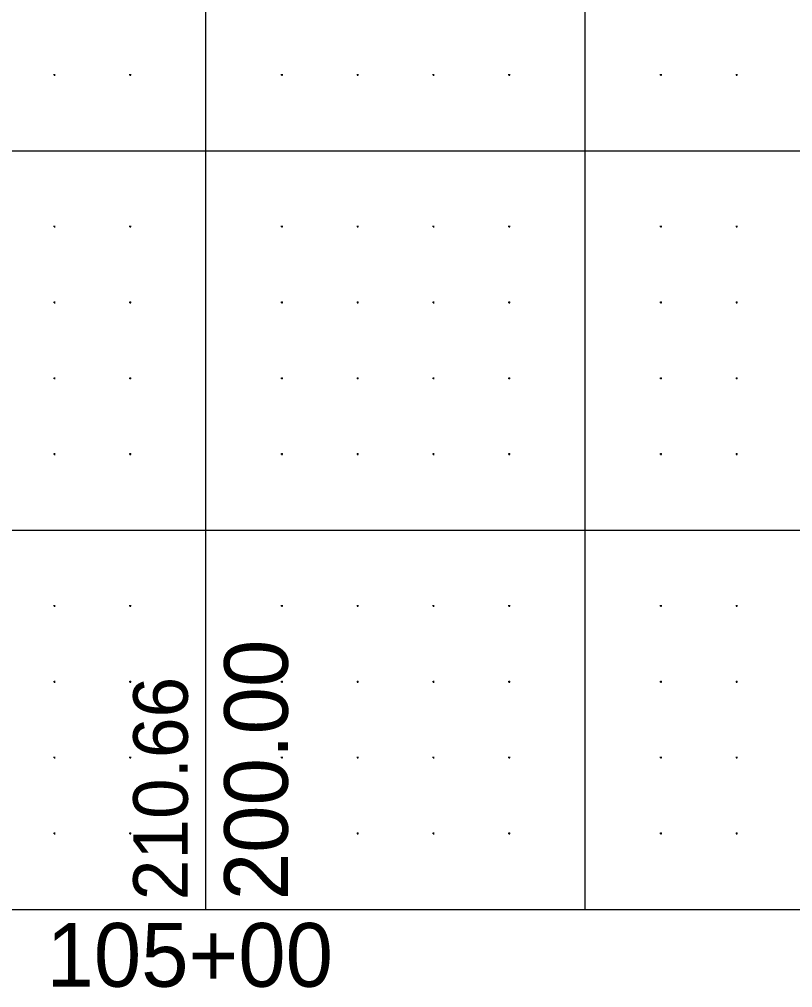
# Model space of a CAD drawing. Extents: x 471 to 2121, y 140 to 650.
# Drawn here: x 1111.4 to 1213.4, y 139.7 to 267.3 of the extents above; entities that cross this region are included whole.
import ezdxf

# ---------------------------------------------------------------- set-up
doc = ezdxf.new("R2010")
doc.units = 0
for name, color, linetype in [('DSN_DRFT_Border Grid', 7, 'Continuous'), ('DSN_RDWY_Prof Annotation', 7, 'Continuous'), ('EX_Profile Annotation', 7, 'Continuous')]:
    doc.layers.add(name, color=color, linetype=linetype)

msp = doc.modelspace()

# ---------------------------------------------------------------- linework, layer by layer
at = {"layer": 'DSN_DRFT_Border Grid'}
for p, q in [((1136.06, 150), (1136.06, 650)), ((1136.06, 150), (1136.06, 650)), ((1186.06, 150), (1186.06, 650)), ((1186.06, 150), (1186.06, 650)), ((1116.18, 260), (1115.94, 260)), ((1116.18, 260), (1115.94, 260)), ((1116.06, 260.12), (1116.06, 259.88)), ((1116.06, 260.12), (1116.06, 259.88)), ((1126.18, 260), (1125.94, 260)), ((1126.18, 260), (1125.94, 260)), ((1126.06, 260.12), (1126.06, 259.88)), ((1126.06, 260.12), (1126.06, 259.88)), ((1146.18, 260), (1145.94, 260)), ((1146.18, 260), (1145.94, 260)), ((1146.06, 260.12), (1146.06, 259.88)), ((1146.06, 260.12), (1146.06, 259.88)), ((1156.18, 260), (1155.94, 260)), ((1156.18, 260), (1155.94, 260)), ((1156.06, 260.12), (1156.06, 259.88)), ((1156.06, 260.12), (1156.06, 259.88)), ((1166.18, 260), (1165.94, 260)), ((1166.18, 260), (1165.94, 260)), ((1166.06, 260.12), (1166.06, 259.88)), ((1166.06, 260.12), (1166.06, 259.88)), ((1176.18, 260), (1175.94, 260)), ((1176.18, 260), (1175.94, 260)), ((1176.06, 260.12), (1176.06, 259.88)), ((1176.06, 260.12), (1176.06, 259.88)), ((1196.18, 260), (1195.94, 260)), ((1196.18, 260), (1195.94, 260)), ((1196.06, 260.12), (1196.06, 259.88)), ((1196.06, 260.12), (1196.06, 259.88)), ((1206.18, 260), (1205.94, 260)), ((1206.18, 260), (1205.94, 260)), ((1206.06, 260.12), (1206.06, 259.88)), ((1206.06, 260.12), (1206.06, 259.88)), ((521.06, 250), (2071.06, 250)), ((521.06, 250), (2071.06, 250)), ((1116.18, 240), (1115.94, 240)), ((1116.18, 240), (1115.94, 240)), ((1116.06, 240.12), (1116.06, 239.88)), ((1116.06, 240.12), (1116.06, 239.88)), ((1126.18, 240), (1125.94, 240)), ((1126.18, 240), (1125.94, 240)), ((1126.06, 240.12), (1126.06, 239.88)), ((1126.06, 240.12), (1126.06, 239.88)), ((1146.18, 240), (1145.94, 240)), ((1146.18, 240), (1145.94, 240)), ((1146.06, 240.12), (1146.06, 239.88)), ((1146.06, 240.12), (1146.06, 239.88)), ((1156.18, 240), (1155.94, 240)), ((1156.18, 240), (1155.94, 240)), ((1156.06, 240.12), (1156.06, 239.88)), ((1156.06, 240.12), (1156.06, 239.88)), ((1166.18, 240), (1165.94, 240)), ((1166.18, 240), (1165.94, 240)), ((1166.06, 240.12), (1166.06, 239.88)), ((1166.06, 240.12), (1166.06, 239.88)), ((1176.18, 240), (1175.94, 240)), ((1176.18, 240), (1175.94, 240)), ((1176.06, 240.12), (1176.06, 239.88)), ((1176.06, 240.12), (1176.06, 239.88)), ((1196.18, 240), (1195.94, 240)), ((1196.18, 240), (1195.94, 240)), ((1196.06, 240.12), (1196.06, 239.88)), ((1196.06, 240.12), (1196.06, 239.88)), ((1206.18, 240), (1205.94, 240)), ((1206.18, 240), (1205.94, 240)), ((1206.06, 240.12), (1206.06, 239.88)), ((1206.06, 240.12), (1206.06, 239.88)), ((1116.18, 230), (1115.94, 230)), ((1116.18, 230), (1115.94, 230)), ((1116.06, 230.12), (1116.06, 229.88)), ((1116.06, 230.12), (1116.06, 229.88)), ((1126.18, 230), (1125.94, 230)), ((1126.18, 230), (1125.94, 230)), ((1126.06, 230.12), (1126.06, 229.88)), ((1126.06, 230.12), (1126.06, 229.88)), ((1146.18, 230), (1145.94, 230)), ((1146.18, 230), (1145.94, 230)), ((1146.06, 230.12), (1146.06, 229.88)), ((1146.06, 230.12), (1146.06, 229.88)), ((1156.18, 230), (1155.94, 230)), ((1156.18, 230), (1155.94, 230)), ((1156.06, 230.12), (1156.06, 229.88)), ((1156.06, 230.12), (1156.06, 229.88)), ((1166.18, 230), (1165.94, 230)), ((1166.18, 230), (1165.94, 230)), ((1166.06, 230.12), (1166.06, 229.88)), ((1166.06, 230.12), (1166.06, 229.88)), ((1176.18, 230), (1175.94, 230)), ((1176.18, 230), (1175.94, 230)), ((1176.06, 230.12), (1176.06, 229.88)), ((1176.06, 230.12), (1176.06, 229.88)), ((1196.18, 230), (1195.94, 230)), ((1196.18, 230), (1195.94, 230)), ((1196.06, 230.12), (1196.06, 229.88)), ((1196.06, 230.12), (1196.06, 229.88)), ((1206.18, 230), (1205.94, 230)), ((1206.18, 230), (1205.94, 230)), ((1206.06, 230.12), (1206.06, 229.88)), ((1206.06, 230.12), (1206.06, 229.88)), ((1116.18, 220), (1115.94, 220)), ((1116.18, 220), (1115.94, 220)), ((1116.06, 220.12), (1116.06, 219.88)), ((1116.06, 220.12), (1116.06, 219.88)), ((1126.18, 220), (1125.94, 220)), ((1126.18, 220), (1125.94, 220)), ((1126.06, 220.12), (1126.06, 219.88)), ((1126.06, 220.12), (1126.06, 219.88)), ((1146.18, 220), (1145.94, 220)), ((1146.18, 220), (1145.94, 220)), ((1146.06, 220.12), (1146.06, 219.88)), ((1146.06, 220.12), (1146.06, 219.88)), ((1156.18, 220), (1155.94, 220)), ((1156.18, 220), (1155.94, 220)), ((1156.06, 220.12), (1156.06, 219.88)), ((1156.06, 220.12), (1156.06, 219.88)), ((1166.18, 220), (1165.94, 220)), ((1166.18, 220), (1165.94, 220)), ((1166.06, 220.12), (1166.06, 219.88)), ((1166.06, 220.12), (1166.06, 219.88)), ((1176.18, 220), (1175.94, 220)), ((1176.18, 220), (1175.94, 220)), ((1176.06, 220.12), (1176.06, 219.88)), ((1176.06, 220.12), (1176.06, 219.88)), ((1196.18, 220), (1195.94, 220)), ((1196.18, 220), (1195.94, 220)), ((1196.06, 220.12), (1196.06, 219.88)), ((1196.06, 220.12), (1196.06, 219.88)), ((1206.18, 220), (1205.94, 220)), ((1206.18, 220), (1205.94, 220)), ((1206.06, 220.12), (1206.06, 219.88)), ((1206.06, 220.12), (1206.06, 219.88)), ((1116.18, 210), (1115.94, 210)), ((1116.18, 210), (1115.94, 210)), ((1116.06, 210.12), (1116.06, 209.88)), ((1116.06, 210.12), (1116.06, 209.88)), ((1126.18, 210), (1125.94, 210)), ((1126.18, 210), (1125.94, 210)), ((1126.06, 210.12), (1126.06, 209.88)), ((1126.06, 210.12), (1126.06, 209.88)), ((1146.18, 210), (1145.94, 210)), ((1146.18, 210), (1145.94, 210)), ((1146.06, 210.12), (1146.06, 209.88)), ((1146.06, 210.12), (1146.06, 209.88)), ((1156.18, 210), (1155.94, 210)), ((1156.18, 210), (1155.94, 210)), ((1156.06, 210.12), (1156.06, 209.88)), ((1156.06, 210.12), (1156.06, 209.88)), ((1166.18, 210), (1165.94, 210)), ((1166.18, 210), (1165.94, 210)), ((1166.06, 210.12), (1166.06, 209.88)), ((1166.06, 210.12), (1166.06, 209.88)), ((1176.18, 210), (1175.94, 210)), ((1176.18, 210), (1175.94, 210)), ((1176.06, 210.12), (1176.06, 209.88)), ((1176.06, 210.12), (1176.06, 209.88)), ((1196.18, 210), (1195.94, 210)), ((1196.18, 210), (1195.94, 210)), ((1196.06, 210.12), (1196.06, 209.88)), ((1196.06, 210.12), (1196.06, 209.88)), ((1206.18, 210), (1205.94, 210)), ((1206.18, 210), (1205.94, 210)), ((1206.06, 210.12), (1206.06, 209.88)), ((1206.06, 210.12), (1206.06, 209.88)), ((521.06, 200), (2071.06, 200)), ((521.06, 200), (2071.06, 200)), ((1116.18, 190), (1115.94, 190)), ((1116.18, 190), (1115.94, 190)), ((1116.06, 190.12), (1116.06, 189.88)), ((1116.06, 190.12), (1116.06, 189.88)), ((1126.18, 190), (1125.94, 190)), ((1126.18, 190), (1125.94, 190)), ((1126.06, 190.12), (1126.06, 189.88)), ((1126.06, 190.12), (1126.06, 189.88)), ((1146.18, 190), (1145.94, 190)), ((1146.18, 190), (1145.94, 190)), ((1146.06, 190.12), (1146.06, 189.88)), ((1146.06, 190.12), (1146.06, 189.88)), ((1156.18, 190), (1155.94, 190)), ((1156.18, 190), (1155.94, 190)), ((1156.06, 190.12), (1156.06, 189.88)), ((1156.06, 190.12), (1156.06, 189.88)), ((1166.18, 190), (1165.94, 190)), ((1166.18, 190), (1165.94, 190)), ((1166.06, 190.12), (1166.06, 189.88)), ((1166.06, 190.12), (1166.06, 189.88)), ((1176.18, 190), (1175.94, 190)), ((1176.18, 190), (1175.94, 190)), ((1176.06, 190.12), (1176.06, 189.88)), ((1176.06, 190.12), (1176.06, 189.88)), ((1196.18, 190), (1195.94, 190)), ((1196.18, 190), (1195.94, 190)), ((1196.06, 190.12), (1196.06, 189.88)), ((1196.06, 190.12), (1196.06, 189.88)), ((1206.18, 190), (1205.94, 190)), ((1206.18, 190), (1205.94, 190)), ((1206.06, 190.12), (1206.06, 189.88)), ((1206.06, 190.12), (1206.06, 189.88)), ((1116.18, 180), (1115.94, 180)), ((1116.18, 180), (1115.94, 180)), ((1116.06, 180.12), (1116.06, 179.88)), ((1116.06, 180.12), (1116.06, 179.88)), ((1126.18, 180), (1125.94, 180)), ((1126.18, 180), (1125.94, 180)), ((1126.06, 180.12), (1126.06, 179.88)), ((1126.06, 180.12), (1126.06, 179.88)), ((1146.18, 180), (1145.94, 180)), ((1146.18, 180), (1145.94, 180)), ((1146.06, 180.12), (1146.06, 179.88)), ((1146.06, 180.12), (1146.06, 179.88)), ((1156.18, 180), (1155.94, 180)), ((1156.18, 180), (1155.94, 180)), ((1156.06, 180.12), (1156.06, 179.88)), ((1156.06, 180.12), (1156.06, 179.88)), ((1166.18, 180), (1165.94, 180)), ((1166.18, 180), (1165.94, 180)), ((1166.06, 180.12), (1166.06, 179.88)), ((1166.06, 180.12), (1166.06, 179.88)), ((1176.18, 180), (1175.94, 180)), ((1176.18, 180), (1175.94, 180)), ((1176.06, 180.12), (1176.06, 179.88)), ((1176.06, 180.12), (1176.06, 179.88)), ((1196.18, 180), (1195.94, 180)), ((1196.18, 180), (1195.94, 180)), ((1196.06, 180.12), (1196.06, 179.88)), ((1196.06, 180.12), (1196.06, 179.88)), ((1206.18, 180), (1205.94, 180)), ((1206.18, 180), (1205.94, 180)), ((1206.06, 180.12), (1206.06, 179.88)), ((1206.06, 180.12), (1206.06, 179.88)), ((1116.18, 170), (1115.94, 170)), ((1116.18, 170), (1115.94, 170)), ((1116.06, 170.12), (1116.06, 169.88)), ((1116.06, 170.12), (1116.06, 169.88)), ((1126.18, 170), (1125.94, 170)), ((1126.18, 170), (1125.94, 170)), ((1126.06, 170.12), (1126.06, 169.88)), ((1126.06, 170.12), (1126.06, 169.88)), ((1146.18, 170), (1145.94, 170)), ((1146.18, 170), (1145.94, 170)), ((1146.06, 170.12), (1146.06, 169.88)), ((1146.06, 170.12), (1146.06, 169.88)), ((1156.18, 170), (1155.94, 170)), ((1156.18, 170), (1155.94, 170)), ((1156.06, 170.12), (1156.06, 169.88)), ((1156.06, 170.12), (1156.06, 169.88)), ((1166.18, 170), (1165.94, 170)), ((1166.18, 170), (1165.94, 170)), ((1166.06, 170.12), (1166.06, 169.88)), ((1166.06, 170.12), (1166.06, 169.88)), ((1176.18, 170), (1175.94, 170)), ((1176.18, 170), (1175.94, 170)), ((1176.06, 170.12), (1176.06, 169.88)), ((1176.06, 170.12), (1176.06, 169.88)), ((1196.18, 170), (1195.94, 170)), ((1196.18, 170), (1195.94, 170)), ((1196.06, 170.12), (1196.06, 169.88)), ((1196.06, 170.12), (1196.06, 169.88)), ((1206.18, 170), (1205.94, 170)), ((1206.18, 170), (1205.94, 170)), ((1206.06, 170.12), (1206.06, 169.88)), ((1206.06, 170.12), (1206.06, 169.88)), ((1116.18, 160), (1115.94, 160)), ((1116.18, 160), (1115.94, 160)), ((1116.06, 160.12), (1116.06, 159.88)), ((1116.06, 160.12), (1116.06, 159.88)), ((1126.18, 160), (1125.94, 160)), ((1126.18, 160), (1125.94, 160)), ((1126.06, 160.12), (1126.06, 159.88)), ((1126.06, 160.12), (1126.06, 159.88)), ((1146.18, 160), (1145.94, 160)), ((1146.18, 160), (1145.94, 160)), ((1146.06, 160.12), (1146.06, 159.88)), ((1146.06, 160.12), (1146.06, 159.88)), ((1156.18, 160), (1155.94, 160)), ((1156.18, 160), (1155.94, 160)), ((1156.06, 160.12), (1156.06, 159.88)), ((1156.06, 160.12), (1156.06, 159.88)), ((1166.18, 160), (1165.94, 160)), ((1166.18, 160), (1165.94, 160)), ((1166.06, 160.12), (1166.06, 159.88)), ((1166.06, 160.12), (1166.06, 159.88)), ((1176.18, 160), (1175.94, 160)), ((1176.18, 160), (1175.94, 160)), ((1176.06, 160.12), (1176.06, 159.88)), ((1176.06, 160.12), (1176.06, 159.88)), ((1196.18, 160), (1195.94, 160)), ((1196.18, 160), (1195.94, 160)), ((1196.06, 160.12), (1196.06, 159.88)), ((1196.06, 160.12), (1196.06, 159.88)), ((1206.18, 160), (1205.94, 160)), ((1206.18, 160), (1205.94, 160)), ((1206.06, 160.12), (1206.06, 159.88)), ((1206.06, 160.12), (1206.06, 159.88)), ((521.06, 150), (2071.06, 150)), ((521.06, 150), (2071.06, 150))]:
    msp.add_line(p, q, dxfattribs=at)

# ---------------------------------------------------------------- texts
at = {"layer": 'DSN_RDWY_Prof Annotation'}
msp.add_text('200.00', height=8.4, rotation=90, dxfattribs=at).set_placement((1146.86, 151.2))
msp.add_text('105+00', height=8.4, dxfattribs=at).set_placement((1115.02, 139.8))
msp.add_text('105+00', height=8.4, dxfattribs=at).set_placement((1115.02, 139.8))
at = {"layer": 'EX_Profile Annotation'}
msp.add_text('210.66', height=7.2, rotation=90, dxfattribs=at).set_placement((1133.66, 151.2))

doc.saveas('drawing.dxf')
